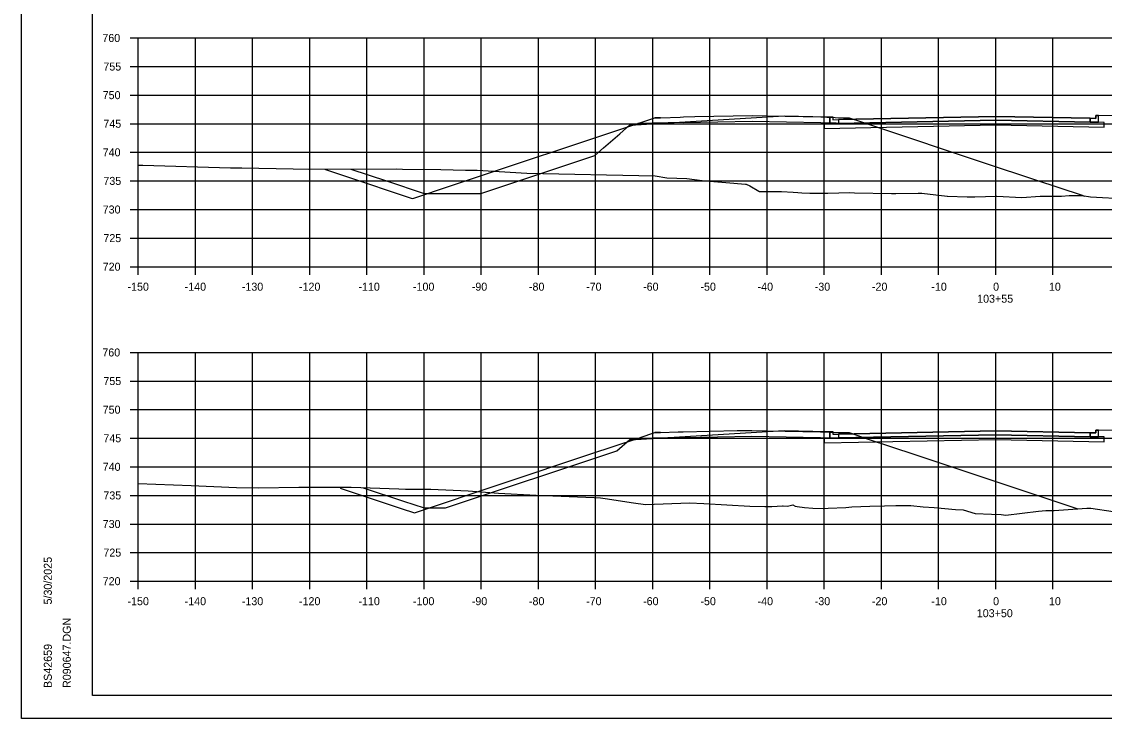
# Model space of a CAD drawing. Extents: x 1202951 to 1376887, y 378065 to 728038.
# Drawn here: x 1374114.6 to 1374304, y 379400 to 379521.8 of the extents above; entities that cross this region are included whole.
import ezdxf

# ---------------------------------------------------------------- set-up
doc = ezdxf.new("R2010")
doc.units = 0
for name, color, linetype in [('Default', 7, 'Continuous'), ('R_Alt Surface', 7, 'Continuous'), ('R_Axis', 7, 'Continuous'), ('R_Axis Annot', 7, 'Continuous'), ('R_Exist Surface', 7, 'Continuous'), ('R_Fin Surface', 7, 'Continuous'), ('R_Grid', 7, 'Continuous'), ('R_No Plot', 7, 'Continuous'), ('R_Proposed Road', 7, 'Continuous')]:
    doc.layers.add(name, color=color, linetype=linetype)

msp = doc.modelspace()

# ---------------------------------------------------------------- linework, layer by layer
at = {"layer": 'Default'}
for points in [[(1374302.98, 379505.37), (1374302.49, 379505.37), (1374302.48, 379504.87), (1374301.48, 379504.89), (1374301.48, 379504.22), (1374302.98, 379504.19)], [(1374255.98, 379505.15), (1374256.47, 379505.15), (1374256.48, 379504.65), (1374257.48, 379504.67), (1374257.48, 379504), (1374255.98, 379503.97)], [(1374302.98, 379450.36), (1374302.49, 379450.36), (1374302.48, 379449.86), (1374301.48, 379449.88), (1374301.48, 379449.21), (1374302.98, 379449.18)], [(1374255.98, 379450.14), (1374256.47, 379450.14), (1374256.48, 379449.64), (1374257.48, 379449.66), (1374257.48, 379448.99), (1374255.98, 379448.96)]]:
    msp.add_lwpolyline(points, close=True, dxfattribs=at)
at = {"layer": 'R_Alt Surface'}
for points in [[(1374255.98, 379505.15), (1374255.98, 379503.97), (1374257.48, 379504), (1374284.98, 379504.55), (1374301.48, 379504.22), (1374302.98, 379504.19), (1374302.98, 379505.37)], [(1374230.37, 379504.14), (1374222.36, 379503.98)], [(1374230.37, 379504.14), (1374242.37, 379504.38), (1374254.37, 379504.14)], [(1374254.37, 379504.14), (1374262.37, 379503.98)], [(1374255.98, 379450.14), (1374255.98, 379448.96), (1374257.48, 379448.99), (1374284.98, 379449.54), (1374301.48, 379449.21), (1374302.98, 379449.18), (1374302.98, 379450.36)], [(1374230.32, 379449.08), (1374222.32, 379448.92)], [(1374230.32, 379449.08), (1374242.32, 379449.32), (1374254.32, 379449.08)], [(1374254.32, 379449.08), (1374262.32, 379448.92)]]:
    msp.add_lwpolyline(points, dxfattribs=at)
for points in [[(1374257.48, 379504.67), (1374257.48, 379504), (1374284.98, 379504.55), (1374301.48, 379504.22), (1374301.48, 379504.89), (1374301.48, 379504.89), (1374284.98, 379505.22), (1374257.48, 379504.67)], [(1374284.98, 379504.55), (1374257.48, 379504), (1374255.98, 379503.97), (1374254.98, 379503.95), (1374254.98, 379503.12), (1374284.98, 379503.72), (1374303.98, 379503.34), (1374303.98, 379504.17), (1374302.98, 379504.19), (1374301.48, 379504.22)], [(1374284.98, 379449.54), (1374257.48, 379448.99), (1374255.98, 379448.96), (1374254.98, 379448.94), (1374254.98, 379448.11), (1374284.98, 379448.71), (1374303.98, 379448.33), (1374303.98, 379449.16), (1374302.98, 379449.18), (1374301.48, 379449.21)], [(1374257.48, 379449.66), (1374257.48, 379448.99), (1374284.98, 379449.54), (1374301.48, 379449.21), (1374301.48, 379449.88), (1374301.48, 379449.88), (1374284.98, 379450.21), (1374257.48, 379449.66)]]:
    msp.add_lwpolyline(points, close=True, dxfattribs=at)
at = {"layer": 'R_Axis'}
for p, q in [((1374133.58, 379518.94), (1374134.98, 379518.94)), ((1374134.98, 379478.94), (1374134.98, 379518.94)), ((1374133.58, 379513.94), (1374134.98, 379513.94)), ((1374133.58, 379508.94), (1374134.98, 379508.94)), ((1374133.58, 379503.94), (1374134.98, 379503.94)), ((1374133.58, 379498.94), (1374134.98, 379498.94)), ((1374133.58, 379493.94), (1374134.98, 379493.94)), ((1374133.58, 379488.94), (1374134.98, 379488.94)), ((1374133.58, 379483.94), (1374134.98, 379483.94)), ((1374133.58, 379478.94), (1374134.98, 379478.94)), ((1374134.98, 379478.94), (1374434.98, 379478.94)), ((1374134.98, 379477.54), (1374134.98, 379478.94)), ((1374144.98, 379477.54), (1374144.98, 379478.94)), ((1374154.98, 379477.54), (1374154.98, 379478.94)), ((1374164.98, 379477.54), (1374164.98, 379478.94)), ((1374174.98, 379477.54), (1374174.98, 379478.94)), ((1374184.98, 379477.54), (1374184.98, 379478.94)), ((1374194.98, 379477.54), (1374194.98, 379478.94)), ((1374204.98, 379477.54), (1374204.98, 379478.94)), ((1374214.98, 379477.54), (1374214.98, 379478.94)), ((1374224.98, 379477.54), (1374224.98, 379478.94)), ((1374234.98, 379477.54), (1374234.98, 379478.94)), ((1374244.98, 379477.54), (1374244.98, 379478.94)), ((1374254.98, 379477.54), (1374254.98, 379478.94)), ((1374264.98, 379477.54), (1374264.98, 379478.94)), ((1374274.98, 379477.54), (1374274.98, 379478.94)), ((1374284.98, 379477.54), (1374284.98, 379478.94)), ((1374294.98, 379477.54), (1374294.98, 379478.94)), ((1374133.58, 379463.94), (1374134.98, 379463.94)), ((1374134.98, 379423.94), (1374134.98, 379463.94)), ((1374133.58, 379458.94), (1374134.98, 379458.94)), ((1374133.58, 379453.94), (1374134.98, 379453.94)), ((1374133.58, 379448.94), (1374134.98, 379448.94)), ((1374133.58, 379443.94), (1374134.98, 379443.94)), ((1374133.58, 379438.94), (1374134.98, 379438.94)), ((1374133.58, 379433.94), (1374134.98, 379433.94)), ((1374133.58, 379428.94), (1374134.98, 379428.94)), ((1374133.58, 379423.94), (1374134.98, 379423.94)), ((1374134.98, 379423.94), (1374434.98, 379423.94)), ((1374134.98, 379422.54), (1374134.98, 379423.94)), ((1374144.98, 379422.54), (1374144.98, 379423.94)), ((1374154.98, 379422.54), (1374154.98, 379423.94)), ((1374164.98, 379422.54), (1374164.98, 379423.94)), ((1374174.98, 379422.54), (1374174.98, 379423.94)), ((1374184.98, 379422.54), (1374184.98, 379423.94)), ((1374194.98, 379422.54), (1374194.98, 379423.94)), ((1374204.98, 379422.54), (1374204.98, 379423.94)), ((1374214.98, 379422.54), (1374214.98, 379423.94)), ((1374224.98, 379422.54), (1374224.98, 379423.94)), ((1374234.98, 379422.54), (1374234.98, 379423.94)), ((1374244.98, 379422.54), (1374244.98, 379423.94)), ((1374254.98, 379422.54), (1374254.98, 379423.94)), ((1374264.98, 379422.54), (1374264.98, 379423.94)), ((1374274.98, 379422.54), (1374274.98, 379423.94)), ((1374284.98, 379422.54), (1374284.98, 379423.94)), ((1374294.98, 379422.54), (1374294.98, 379423.94))]:
    msp.add_line(p, q, dxfattribs=at)
at = {"layer": 'R_Exist Surface'}
for points in [[(1374134.98, 379496.7), (1374135.79, 379496.7), (1374151.09, 379496.25), (1374153.08, 379496.24), (1374162.05, 379496.03), (1374164.84, 379495.97), (1374180.13, 379496.05), (1374181.21, 379496.01), (1374187.91, 379495.96), (1374192.25, 379495.84), (1374194.27, 379495.83), (1374202.98, 379495.27), (1374211.34, 379495.14), (1374216.88, 379495.03), (1374225.43, 379494.81), (1374227.46, 379494.5), (1374230.96, 379494.34), (1374233.62, 379494.02), (1374241.19, 379493.39), (1374241.32, 379493.37), (1374241.98, 379493.06), (1374243.56, 379492.15), (1374243.62, 379492.1), (1374246.7, 379492.1), (1374247.48, 379492.06), (1374249.53, 379491.97), (1374250.35, 379491.89), (1374251.04, 379491.83), (1374252.47, 379491.8), (1374254.64, 379491.8), (1374255.63, 379491.81), (1374259.45, 379491.89), (1374260.28, 379491.83), (1374266.74, 379491.75), (1374267.5, 379491.76), (1374271.41, 379491.79), (1374272.03, 379491.77), (1374276.49, 379491.3), (1374276.55, 379491.29), (1374279.98, 379491.16), (1374280.58, 379491.14), (1374280.59, 379491.14), (1374281.34, 379491.16), (1374285.07, 379491.3), (1374285.2, 379491.3), (1374289.57, 379491.06), (1374292.73, 379491.28), (1374293.9, 379491.28), (1374296.46, 379491.3), (1374297.84, 379491.4), (1374300.09, 379491.37), (1374301.55, 379491.15), (1374307.94, 379490.82)], [(1374134.98, 379441.03), (1374144.25, 379440.65), (1374152.18, 379440.33), (1374155.98, 379440.29), (1374163.09, 379440.39), (1374172.2, 379440.37), (1374180.53, 379440.07), (1374181.74, 379440.04), (1374186.18, 379440.01), (1374192.67, 379439.75), (1374198, 379439.36), (1374204.56, 379439), (1374214.72, 379438.55), (1374215.84, 379438.49), (1374216.67, 379438.42), (1374221.62, 379437.65), (1374223.74, 379437.37), (1374231.4, 379437.65), (1374233.89, 379437.52), (1374241.94, 379437.03), (1374244.61, 379436.98), (1374245.83, 379437), (1374247.7, 379437.12), (1374247.78, 379437.12), (1374248.58, 379437.08), (1374249.51, 379437.32), (1374249.89, 379437.05), (1374250.23, 379436.98), (1374251.5, 379436.85), (1374253, 379436.72), (1374254.81, 379436.68), (1374255.67, 379436.69), (1374258.78, 379436.83), (1374259.83, 379436.95), (1374262.94, 379437.05), (1374265.53, 379437.14), (1374267.5, 379437.16), (1374268.79, 379437.15), (1374269.44, 379437.16), (1374270.11, 379437.19), (1374272.31, 379436.92), (1374274.22, 379436.8), (1374277.95, 379436.47), (1374279.26, 379436.4), (1374281.38, 379435.79), (1374284.25, 379435.67), (1374285.91, 379435.61), (1374286.76, 379435.46), (1374292.47, 379436.2), (1374293.74, 379436.29), (1374295.23, 379436.3), (1374300.94, 379436.7), (1374301.64, 379436.69), (1374305.52, 379436.1)]]:
    msp.add_lwpolyline(points, dxfattribs=at)
at = {"layer": 'R_Fin Surface'}
for points in [[(1374167.6, 379495.99), (1374167.71, 379495.95), (1374171.2, 379494.79), (1374182.69, 379490.95), (1374182.99, 379490.85), (1374189.76, 379493.11), (1374222.36, 379503.98), (1374222.73, 379504.1), (1374225.37, 379504.98), (1374226.23, 379504.98), (1374226.36, 379504.98), (1374229.78, 379505.11), (1374230.37, 379505.14), (1374232.34, 379505.18), (1374242.37, 379505.38), (1374245.04, 379505.33), (1374254.37, 379505.14), (1374255.44, 379505.1), (1374258.37, 379504.98), (1374259.09, 379504.98), (1374259.37, 379504.98), (1374261.49, 379504.28), (1374262.37, 379503.98), (1374283.84, 379496.83), (1374291.04, 379494.44), (1374291.96, 379494.13), (1374300.12, 379491.42), (1374300.23, 379491.38), (1374300.48, 379491.29)], [(1374172.17, 379496.01), (1374178.38, 379493.94), (1374184.98, 379491.74), (1374187.86, 379491.74), (1374192.41, 379491.74), (1374194.88, 379491.74), (1374214.86, 379498.41), (1374216.39, 379499.75), (1374219.21, 379502.19), (1374220.98, 379503.74), (1374221.98, 379503.74), (1374247.98, 379505.31), (1374252.98, 379505.21), (1374255.98, 379505.15), (1374256.47, 379505.15), (1374256.48, 379504.65), (1374257.48, 379504.67), (1374284.98, 379505.22), (1374301.48, 379504.89), (1374302.48, 379504.87), (1374302.49, 379505.37), (1374302.98, 379505.37), (1374305.98, 379505.43)], [(1374170.31, 379440.23), (1374177.3, 379437.9), (1374180.95, 379436.68), (1374183.28, 379435.9), (1374214.15, 379446.19), (1374222.32, 379448.92), (1374224.65, 379449.69), (1374225.32, 379449.92), (1374226.1, 379449.92), (1374226.32, 379449.92), (1374229.43, 379450.04), (1374230.32, 379450.08), (1374239.73, 379450.27), (1374242.32, 379450.32), (1374245.06, 379450.26), (1374254.32, 379450.08), (1374257.46, 379449.95), (1374258.32, 379449.92), (1374259.11, 379449.92), (1374259.32, 379449.92), (1374261.68, 379449.13), (1374262.32, 379448.92), (1374271.02, 379446.02), (1374299.32, 379436.59)], [(1374174.32, 379440.29), (1374181.37, 379437.94), (1374184.98, 379436.74), (1374188.7, 379436.74), (1374218.69, 379446.74), (1374220.98, 379448.74), (1374221.98, 379448.74), (1374247.98, 379450.3), (1374252.98, 379450.2), (1374255.98, 379450.14), (1374256.47, 379450.14), (1374256.48, 379449.64), (1374257.48, 379449.66), (1374284.98, 379450.21), (1374301.48, 379449.88), (1374302.48, 379449.86), (1374302.49, 379450.36), (1374302.98, 379450.36), (1374305.98, 379450.42), (1374310.98, 379450.52), (1374312.32, 379450.07), (1374355.92, 379435.54), (1374356.37, 379435.69)]]:
    msp.add_lwpolyline(points, dxfattribs=at)
at = {"layer": 'R_Grid'}
for p, q in [((1374134.98, 379518.94), (1374434.98, 379518.94)), ((1374134.98, 379478.94), (1374134.98, 379518.94)), ((1374144.98, 379478.94), (1374144.98, 379518.94)), ((1374154.98, 379478.94), (1374154.98, 379518.94)), ((1374164.98, 379478.94), (1374164.98, 379518.94)), ((1374174.98, 379478.94), (1374174.98, 379518.94)), ((1374184.98, 379478.94), (1374184.98, 379518.94)), ((1374194.98, 379478.94), (1374194.98, 379518.94)), ((1374204.98, 379478.94), (1374204.98, 379518.94)), ((1374214.98, 379478.94), (1374214.98, 379518.94)), ((1374224.98, 379478.94), (1374224.98, 379518.94)), ((1374234.98, 379478.94), (1374234.98, 379518.94)), ((1374244.98, 379478.94), (1374244.98, 379518.94)), ((1374254.98, 379478.94), (1374254.98, 379518.94)), ((1374264.98, 379478.94), (1374264.98, 379518.94)), ((1374274.98, 379478.94), (1374274.98, 379518.94)), ((1374284.98, 379478.94), (1374284.98, 379518.94)), ((1374294.98, 379478.94), (1374294.98, 379518.94)), ((1374134.98, 379513.94), (1374434.98, 379513.94)), ((1374134.98, 379508.94), (1374434.98, 379508.94)), ((1374134.98, 379503.94), (1374434.98, 379503.94)), ((1374134.98, 379498.94), (1374434.98, 379498.94)), ((1374134.98, 379493.94), (1374434.98, 379493.94)), ((1374134.98, 379488.94), (1374434.98, 379488.94)), ((1374134.98, 379483.94), (1374434.98, 379483.94)), ((1374134.98, 379478.94), (1374434.98, 379478.94)), ((1374134.98, 379463.94), (1374434.98, 379463.94)), ((1374134.98, 379423.94), (1374134.98, 379463.94)), ((1374144.98, 379423.94), (1374144.98, 379463.94)), ((1374154.98, 379423.94), (1374154.98, 379463.94)), ((1374164.98, 379423.94), (1374164.98, 379463.94)), ((1374174.98, 379423.94), (1374174.98, 379463.94)), ((1374184.98, 379423.94), (1374184.98, 379463.94)), ((1374194.98, 379423.94), (1374194.98, 379463.94)), ((1374204.98, 379423.94), (1374204.98, 379463.94)), ((1374214.98, 379423.94), (1374214.98, 379463.94)), ((1374224.98, 379423.94), (1374224.98, 379463.94)), ((1374234.98, 379423.94), (1374234.98, 379463.94)), ((1374244.98, 379423.94), (1374244.98, 379463.94)), ((1374254.98, 379423.94), (1374254.98, 379463.94)), ((1374264.98, 379423.94), (1374264.98, 379463.94)), ((1374274.98, 379423.94), (1374274.98, 379463.94)), ((1374284.98, 379423.94), (1374284.98, 379463.94)), ((1374294.98, 379423.94), (1374294.98, 379463.94)), ((1374134.98, 379458.94), (1374434.98, 379458.94)), ((1374134.98, 379453.94), (1374434.98, 379453.94)), ((1374134.98, 379448.94), (1374434.98, 379448.94)), ((1374134.98, 379443.94), (1374434.98, 379443.94)), ((1374134.98, 379438.94), (1374434.98, 379438.94)), ((1374134.98, 379433.94), (1374434.98, 379433.94)), ((1374134.98, 379428.94), (1374434.98, 379428.94)), ((1374134.98, 379423.94), (1374434.98, 379423.94))]:
    msp.add_line(p, q, dxfattribs=at)
at = {"layer": 'R_No Plot'}
for p, q in [((1374126.98, 379403.94), (1374126.98, 379609.4)), ((1374126.98, 379403.94), (1374126.98, 379403.94)), ((1374443.16, 379403.94), (1374126.98, 379403.94)), ((1374114.58, 379399.96), (1374447.91, 379399.96))]:
    msp.add_line(p, q, dxfattribs=at)
for points in [[(1374114.57, 379613.29), (1374447.91, 379613.29), (1374447.91, 379399.95), (1374114.57, 379399.95)], [(1374360.9, 379609.4), (1374380.52, 379609.4), (1374380.52, 379599.52), (1374396.63, 379599.52), (1374419.83, 379599.52), (1374419.83, 379575.18), (1374443.16, 379575.18), (1374443.16, 379403.94), (1374126.98, 379403.94), (1374126.98, 379609.4)]]:
    msp.add_lwpolyline(points, close=True, dxfattribs=at)
at = {"layer": 'R_Proposed Road'}
for points in [[(1374226.36, 379504.98), (1374225.37, 379504.98)], [(1374258.37, 379504.98), (1374259.37, 379504.98)], [(1374226.32, 379449.92), (1374225.32, 379449.92)], [(1374258.32, 379449.92), (1374259.32, 379449.92)]]:
    msp.add_lwpolyline(points, dxfattribs=at)

# ---------------------------------------------------------------- texts
at = {"layer": 'R_Axis Annot'}
for s, p in [('760', (1374128.69, 379518.24)), ('755', (1374128.87, 379513.24)), ('750', (1374128.75, 379508.24)), ('745', (1374128.87, 379503.24)), ('740', (1374128.75, 379498.24)), ('735', (1374128.87, 379493.24)), ('730', (1374128.75, 379488.24)), ('725', (1374128.87, 379483.24)), ('720', (1374128.75, 379478.24)), ('-150', (1374133.09, 379474.74)), ('-140', (1374143.09, 379474.74)), ('-130', (1374153.09, 379474.74)), ('-120', (1374163.09, 379474.74)), ('-110', (1374173.49, 379474.74)), ('-100', (1374183.03, 379474.74)), ('-90', (1374193.32, 379474.74)), ('-80', (1374203.32, 379474.74)), ('-70', (1374213.32, 379474.74)), ('-60', (1374223.29, 379474.74)), ('-50', (1374233.32, 379474.74)), ('-40', (1374243.32, 379474.74)), ('-30', (1374253.32, 379474.74)), ('-20', (1374263.32, 379474.74)), ('-10', (1374273.72, 379474.74)), ('0', (1374284.52, 379474.74)), ('10', (1374294.29, 379474.74)), ('103+55', (1374281.73, 379472.64)), ('760', (1374128.69, 379463.24)), ('755', (1374128.87, 379458.24)), ('750', (1374128.75, 379453.24)), ('745', (1374128.87, 379448.24)), ('740', (1374128.75, 379443.24)), ('735', (1374128.87, 379438.24)), ('730', (1374128.75, 379433.24)), ('725', (1374128.87, 379428.24)), ('720', (1374128.75, 379423.24)), ('-150', (1374133.09, 379419.74)), ('-140', (1374143.09, 379419.74)), ('-130', (1374153.09, 379419.74)), ('-120', (1374163.09, 379419.74)), ('-110', (1374173.49, 379419.74)), ('-100', (1374183.03, 379419.74)), ('-90', (1374193.32, 379419.74)), ('-80', (1374203.32, 379419.74)), ('-70', (1374213.32, 379419.74)), ('-60', (1374223.29, 379419.74)), ('-50', (1374233.32, 379419.74)), ('-40', (1374243.32, 379419.74)), ('-30', (1374253.32, 379419.74)), ('-20', (1374263.32, 379419.74)), ('-10', (1374273.72, 379419.74)), ('0', (1374284.52, 379419.74)), ('10', (1374294.29, 379419.74)), ('103+50', (1374281.67, 379417.64))]:
    msp.add_text(s, height=1.4, dxfattribs=at).set_placement(p)
at = {"layer": 'R_No Plot'}
for s, p in [('5/30/2025', (1374119.85, 379419.86)), ('R090647.DGN', (1374123.17, 379405.26)), ('BS42659', (1374119.85, 379405.26))]:
    msp.add_text(s, height=1.4, rotation=90, dxfattribs=at).set_placement(p)

doc.saveas('drawing.dxf')
